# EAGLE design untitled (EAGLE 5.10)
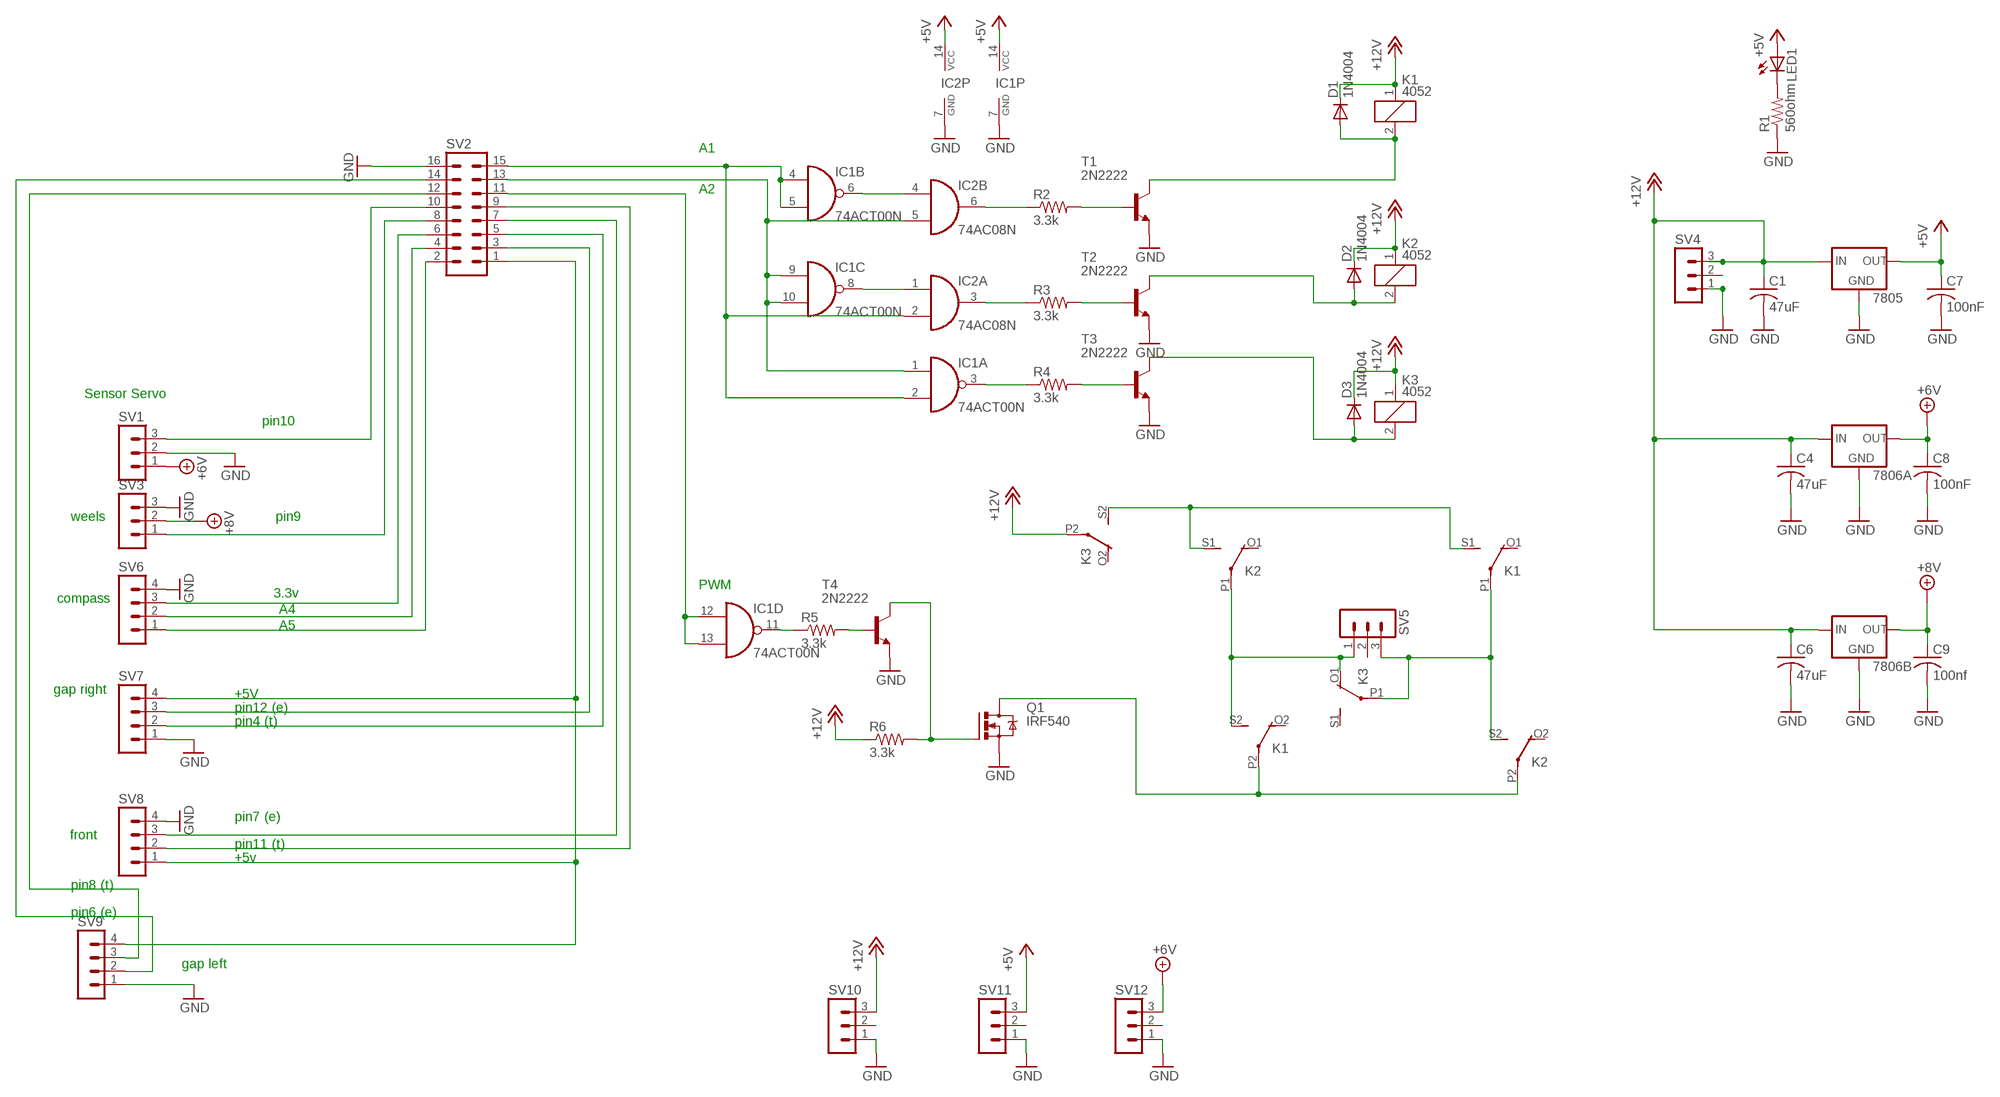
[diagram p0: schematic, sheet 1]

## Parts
7805  78XXL  [78XXL]
7806A  78XXL  [78XXL]
7806B  78XXL  [78XXL]
C1  47uF  C-US025-025X050  [C025-025X050]
C4  47uF  C-US025-025X050  [C025-025X050]
C6  47uF  C-US025-025X050  [C025-025X050]
C7  100nF  C-US025-024X044  [C025-024X044]
C8  100nF  C-US025-024X044  [C025-024X044]
C9  100nf  C-US025-024X044  [C025-024X044]
D1  1N4004  [DO41-10]
D2  1N4004  [DO41-10]
D3  1N4004  [DO41-10]
IC1  74ACT00N  [DIL14]
IC2  74AC08N  [DIL14]
K1  4052  [F4052]
K2  4052  [F4052]
K3  4052  [F4052]
LED1  LED5MM  [LED5MM]
Q1  IRF540  [TO220BV]
R1  560ohm  R-US_0204/7  [0204/7]
R2  3.3k  R-US_0204/7  [0204/7]
R3  3.3k  R-US_0204/7  [0204/7]
R4  3.3k  R-US_0204/7  [0204/7]
R5  3.3k  R-US_0204/7  [0204/7]
R6  3.3k  R-US_0204/7  [0204/7]
SV1  MA03-1  [MA03-1]
SV2  MA08-2  [MA08-2]
SV3  MA03-1  [MA03-1]
SV4  MA03-1  [MA03-1]
SV5  MA03-1  [MA03-1]
SV6  MA04-1  [MA04-1]
SV7  MA04-1  [MA04-1]
SV8  MA04-1  [MA04-1]
SV9  MA04-1  [MA04-1]
SV10  MA03-1  [MA03-1]
SV11  MA03-1  [MA03-1]
SV12  MA03-1  [MA03-1]
T1  2N2222  [TO92-EBC-OVAL]
T2  2N2222  [TO92-EBC-OVAL]
T3  2N2222  [TO92-EBC-OVAL]
T4  2N2222  [TO92-EBC-OVAL]

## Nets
+5V: 7805.OUT C7.1 IC1.14(P:VCC) IC2.14(P:VCC) LED1.A SV11.3
+7V [isxios]: 7806A.OUT C8.1 SV1.1 SV12.3 ; supply symbol labelled +6V
+8V [isxios]: 7806B.OUT C9.1 SV3.2
+12V [isxios]: 7805.IN 7806A.IN 7806B.IN C1.1 C4.1 C6.1 D1.C D2.C D3.C K1.1 K2.1 K3.1 K3.P2(3:P) R6.1 SV4.3 SV10.3
GND: 7805.GND 7806A.GND 7806B.GND C1.2 C4.2 C6.2 C7.2 C8.2 C9.2 IC1.7(P:GND) IC2.7(P:GND) Q1.S R1.1 SV1.2 SV2.16 SV3.3 SV4.1 SV6.4 SV7.1 SV8.4 SV9.1 SV10.1 SV11.1 SV12.1 T1.E T2.E T3.E T4.E
N$1: SV2.2 SV6.1
N$2: LED1.K(C) R1.2
N$3 [isxios]: K1.P2(3:P) K2.P2(3:P) Q1.D
N$4: IC1.2(A:I1) IC1.4(B:I0) IC1.5(B:I1) IC2.2(A:I1) SV2.15
N$5: IC1.6(B:O) IC2.4(B:I0)
N$6: IC1.1(A:I0) IC1.9(C:I0) IC1.10(C:I1) IC2.5(B:I1) SV2.13
N$7: IC1.8(C:O) IC2.1(A:I0)
N$8: IC2.6(B:O) R2.1
N$9: R2.2 T1.B
N$10: IC2.3(A:O) R3.1
N$11: R3.2 T2.B
N$12: IC1.3(A:O) R4.1
N$13: R4.2 T3.B
N$14 [isxios]: D1.A K1.2 T1.C
N$15 [isxios]: D2.A K2.2 T2.C
N$16 [isxios]: D3.A K3.2 T3.C
N$17: SV2.4 SV6.2
N$18: SV2.6 SV6.3
N$19: SV2.8 SV3.1
N$20: SV1.3 SV2.10
N$21: IC1.12(D:I0) IC1.13(D:I1) SV2.11
N$22: IC1.11(D:O) R5.1
N$23: R5.2 T4.B
N$24 [isxios]: Q1.G R6.2 T4.C
N$25 [isxios]: K1.S1(2:S) K2.S1(2:S) K3.S2(3:S)
N$26 [isxios]: K1.P1(2:P) K2.S2(3:S) K3.P1(2:P) SV5.3
N$27 [isxios]: K1.S2(3:S) K2.P1(2:P) K3.O1(2:O) SV5.1
N$28: SV2.1 SV7.4 SV8.1 SV9.4
N$29: SV2.3 SV7.3
N$30: SV2.5 SV7.2
N$31: SV2.7 SV8.3
N$32: SV2.9 SV8.2
N$33: SV2.12 SV9.3
N$34: SV2.14 SV9.2
Unconnected: IC2.8(C:O) IC2.9(C:I0) IC2.10(C:I1) IC2.11(D:O) IC2.12(D:I0) IC2.13(D:I1) K1.O1(2:O) K1.O2(3:O) K2.O1(2:O) K2.O2(3:O) K3.O2(3:O) K3.S1(2:S) SV4.2 SV5.2 SV10.2 SV11.2 SV12.2

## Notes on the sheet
- A1
- A2
- Sensor Servo
- pin10
- weels | pin9
- PWM
- 3.3v
- compass
- A4
- A5
- gap right
- +5V
- pin12 (e)
- pin4 (t)
- pin7 (e)
- front
- pin11 (t)
- +5v
- pin8 (t)
- pin6 (e)
- gap left

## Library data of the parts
7805 7806A 7806B = v-reg:78XXL: VOLTAGE REGULATOR
C1 C4 C6 = adafruit:C-US: CAPACITOR, American symbol
C7-C9 = rcl:C-US: CAPACITOR, American symbol
D1-D3 = adafruit:1N4004: DIODE
IC1 = 74xx-eu:74*00: Quad 2-input NAND gate
IC2 = 74xx-eu:74*08: Quad 2-input AND gate
K1-K3 = relay:4052: RELAY 2 x switch, Finder
LED1 = adafruit:LED: LED
Q1 = transistor-power:IRF540: HEXFET Power MOSFET
R1 = rcl:R-US_: RESISTOR, American symbol
R2-R6 = adafruit:R-US_: RESISTOR, American symbol
SV1 SV3-SV5 SV10-SV12 = con-lstb:MA03-1: PIN HEADER
SV2 = con-lstb:MA08-2: PIN HEADER
SV6-SV9 = con-lstb:MA04-1: PIN HEADER
T1-T4 = adafruit:2N2222: NPN TRANSISTOR Big oval pads

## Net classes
0 default: width 0.8 mm
1 isxios: width 1.6 mm, drill 0.127 mm

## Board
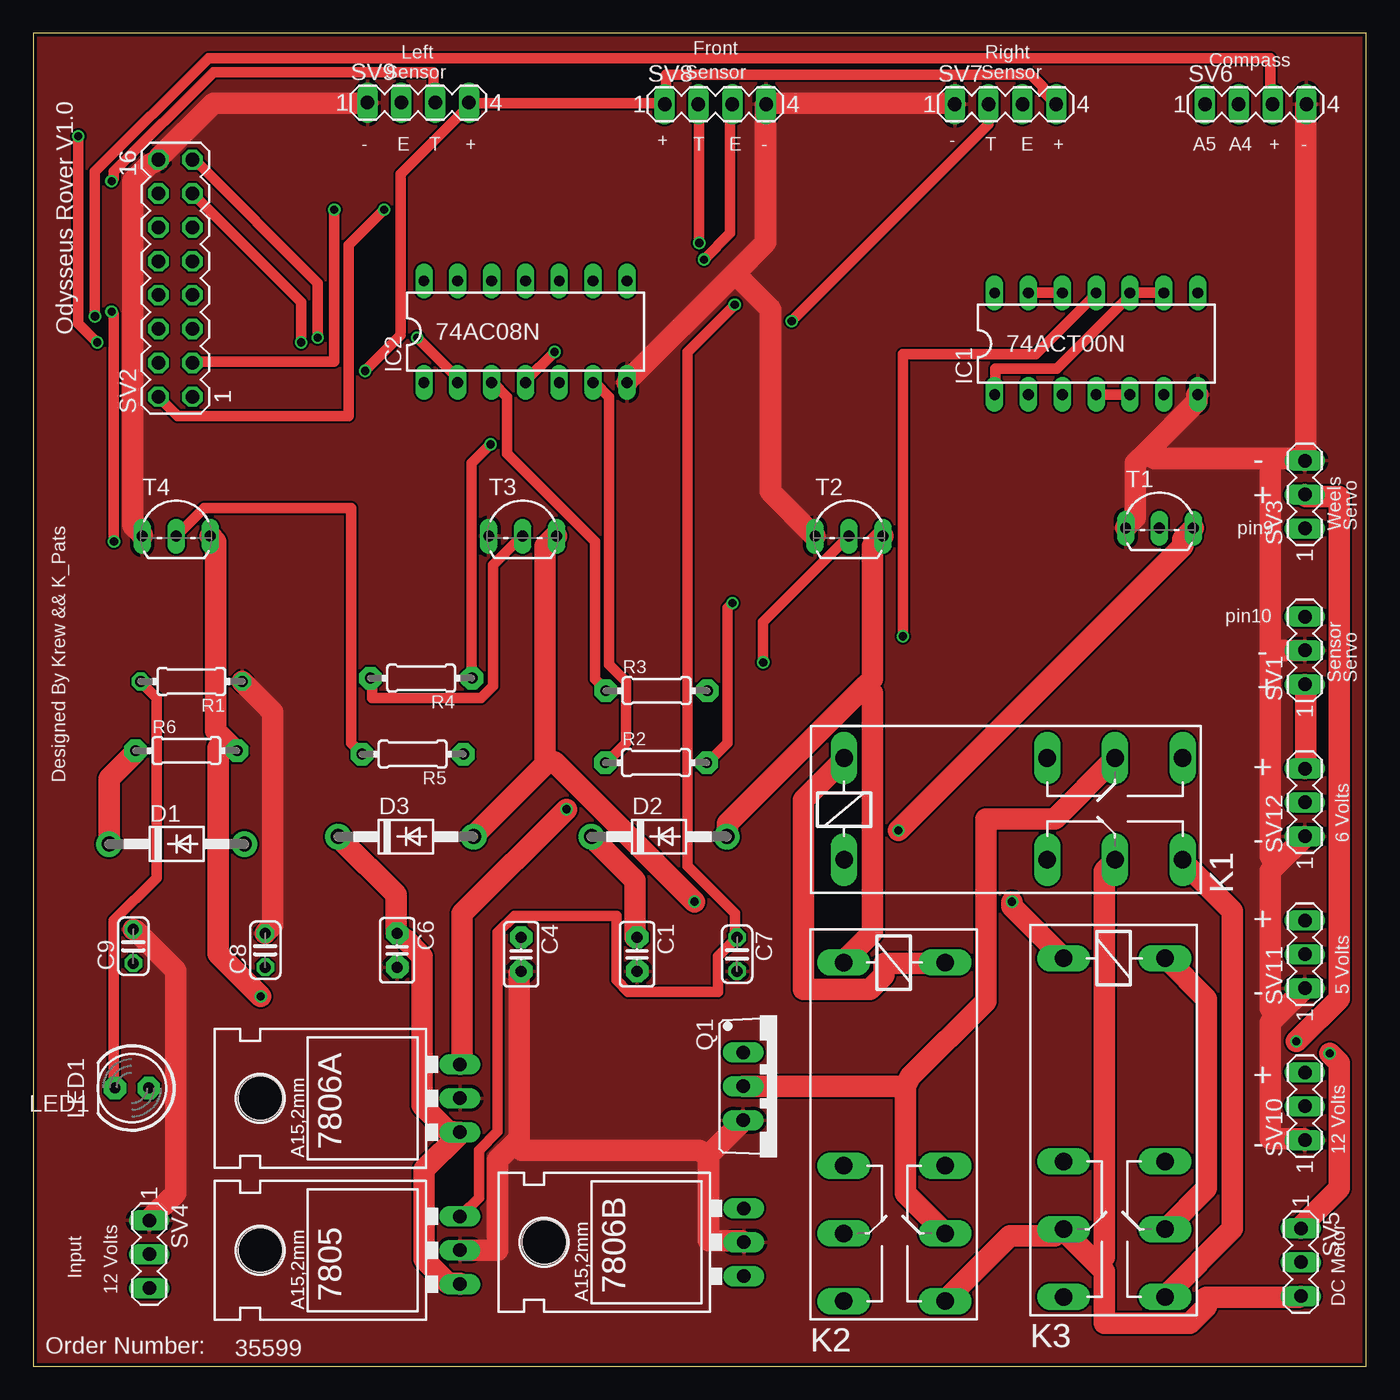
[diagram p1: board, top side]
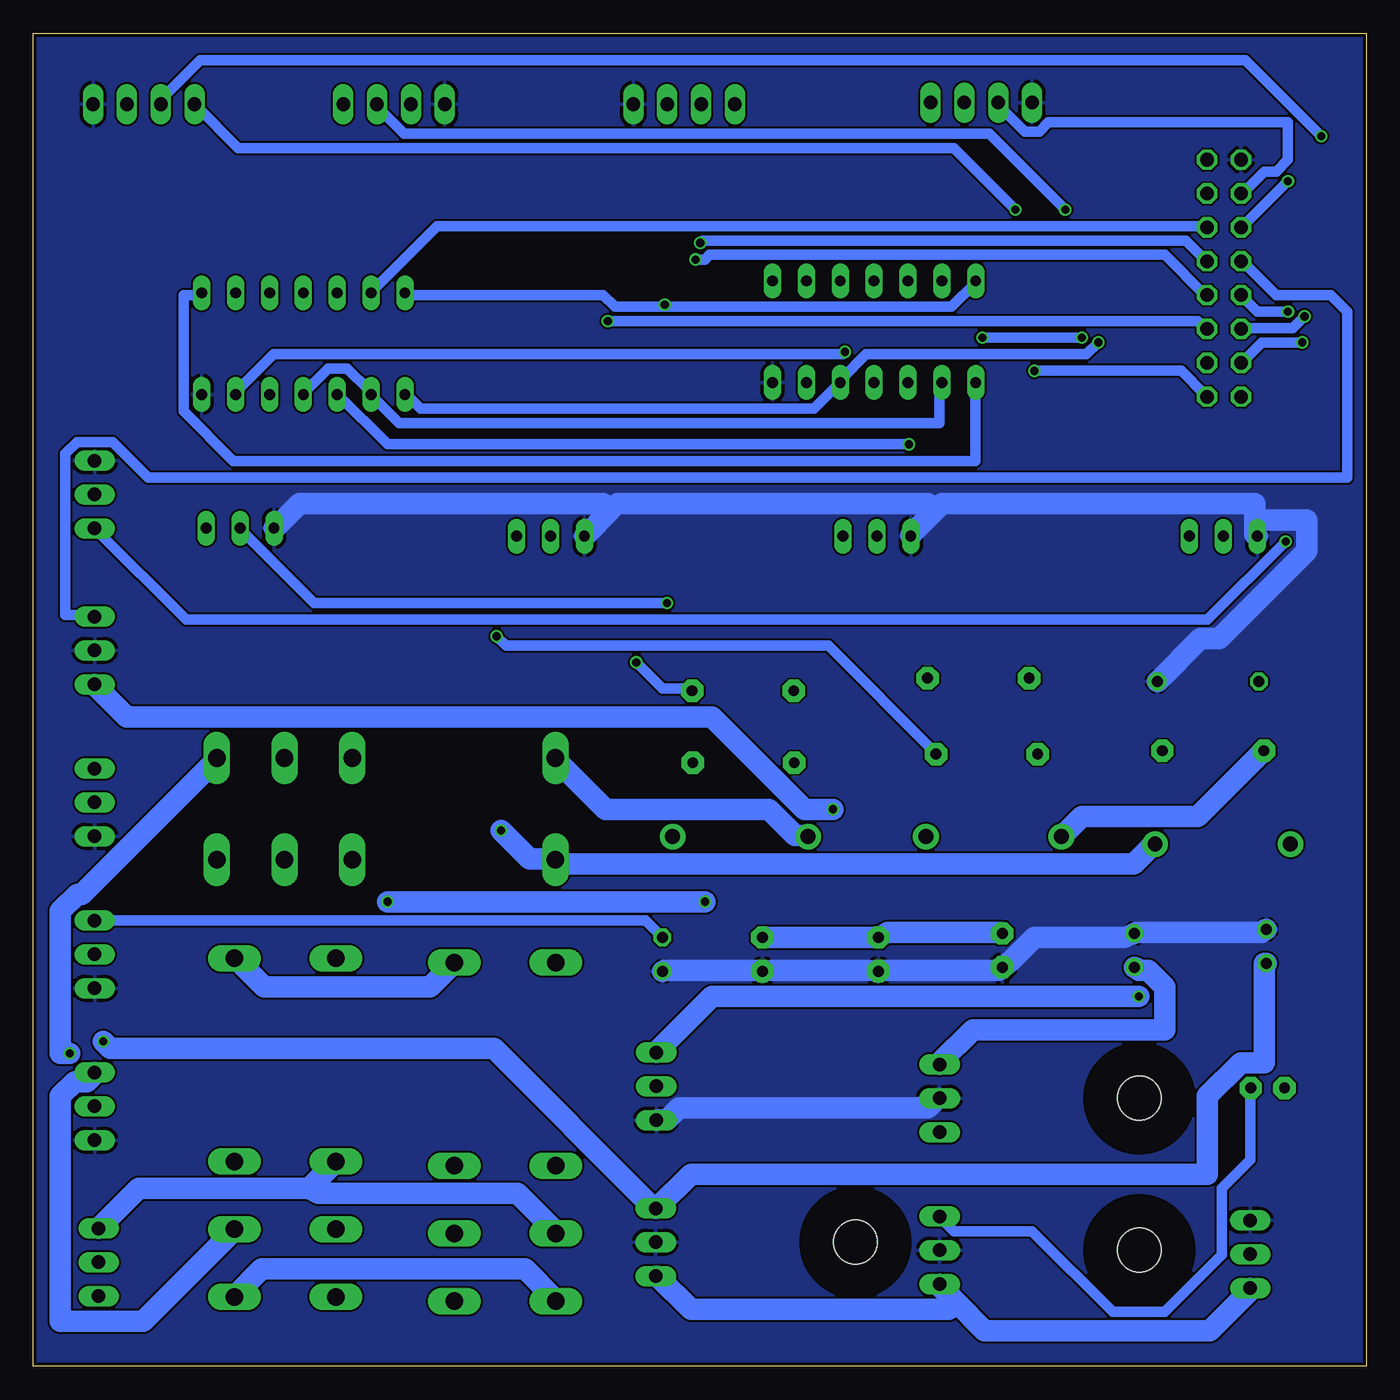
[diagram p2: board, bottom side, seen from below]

Size 100 x 100 mm. Coordinates in mm from the lower left corner, seen from the top.
Outline: 0,0 100,0 100,100 0,100 0,0
Copper layers (1*16): Top 0.035mm / dielectric 1.5mm / Bottom 0.035mm
Design rules "Fusion_eagle_rule_v1.1": minimum track width 6mil, minimum drill 12mil, track to track 6mil, track to pad 6mil, pad to pad 6mil, via to via 6mil, smd to smd 0mil, copper to edge 10mil, drill to drill 10mil, minimum pad ring 10mil, minimum via ring 6mil, stop-mask expansion 2mil, vias tented up to drill 100mil, thermal gap 10mil

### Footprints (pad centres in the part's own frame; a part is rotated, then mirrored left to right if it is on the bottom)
78XXL = drill 1.016 long: GND 0,-3.81; IN -2.54,-3.81; OUT 2.54,-3.81 | hole 3.302: 0,11.176
C025-025X050 = drill 0.813 pad 1.676 octagon: 1 -1.27,0; 2 1.27,0
C025-024X044 = drill 0.813 octagon: 1 -1.27,0; 2 1.27,0
DO41-10 = drill 1.118 pad 1.93 round: A 5.08,0; C -5.08,0
DIL14 = drill 0.813 long: 1 -7.62,-3.81; 2 -5.08,-3.81; 3 -2.54,-3.81; 4 0,-3.81; 5 2.54,-3.81; 6 5.08,-3.81; 7 7.62,-3.81; 8 7.62,3.81; 9 5.08,3.81; 10 2.54,3.81; 11 0,3.81; 12 -2.54,3.81; 13 -5.08,3.81; 14 -7.62,3.81
F4052 = drill 1.321 long: 1 -3.81,3.81; 2 -3.81,-3.81; O1 11.43,-3.81; O2 11.43,3.81; P1 16.51,-3.81; P2 16.51,3.81; S1 21.59,-3.81; S2 21.59,3.81
LED5MM = drill 0.813 pad 1.676 octagon: A -1.27,0; K 1.27,0
TO220BV = drill 1.016 long: D 0,-2.54; G -2.54,-2.54; S 2.54,-2.54
0204/7 = drill 0.813 octagon: 1 -3.81,0; 2 3.81,0
0204/7' = drill 0.813 pad 1.676 octagon: 1 -3.81,0; 2 3.81,0
MA03-1 = drill 1.016 long: 1 -2.54,0; 2 0,0; 3 2.54,0
MA08-2 = drill 1.016 octagon: 1 -8.89,-1.27; 2 -8.89,1.27; 3 -6.35,-1.27; 4 -6.35,1.27; 5 -3.81,-1.27; 6 -3.81,1.27; 7 -1.27,-1.27; 8 -1.27,1.27; 9 1.27,-1.27; 10 1.27,1.27; 11 3.81,-1.27; 12 3.81,1.27; 13 6.35,-1.27; 14 6.35,1.27; 15 8.89,-1.27; 16 8.89,1.27
MA04-1 = drill 1.016 long: 1 -3.81,0; 2 -1.27,0; 3 1.27,0; 4 3.81,0
TO92-EBC-OVAL = drill 0.813 long: B 0,-1.27; C 2.54,-1.27; E -2.54,-1.27

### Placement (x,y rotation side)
7805  28.2,8.7 90 top
7806A  28.2,20.1 90 top
7806B  49.5,9.3 90 top
C1  45.3,30.9 270 top
C4  36.6,30.9 270 top
C6  27.3,31.2 270 top
C7  52.8,30.9 270 top
C8  17.4,31.2 90 top
C9  7.5,31.5 90 top
D1  10.76,39.17 0 top
D2  46.95,39.73 0 top
D3  27.95,39.73 0 top
IC1  79.74,76.71 0 top
IC2  36.92,77.61 0 top
K1  64.64,41.82 0 top
K2  64.61,26.47 270 top
K3  81.11,26.79 270 top
LED1  7.39,20.87 180 top
Q1  55.8,21 270 top
R1  11.86,51.37 180 top
R2  3.3k  [0204/7']  46.72,45.28 0 top
R3  3.3k  [0204/7']  46.76,50.68 0 top
R4  3.3k  [0204/7']  29.1,51.62 180 top
R5  3.3k  [0204/7']  28.46,45.92 180 top
R6  3.3k  [0204/7']  11.48,46.18 0 top
SV1  95.4,53.7 90 top
SV2  10.66,81.63 90 top
SV3  95.4,65.4 90 top
SV4  8.7,8.4 270 top
SV5  95.1,7.8 270 top
SV6  91.71,94.68 0 top
SV7  72.94,94.68 0 top
SV8  51.17,94.68 0 top
SV9  28.88,94.8 0 top
SV10  95.4,19.5 90 top
SV11  95.4,30.9 90 top
SV12  95.4,42.3 90 top
T1  84.49,64.14 0 top
T2  61.2,63.54 0 top
T3  36.71,63.54 0 top
T4  10.72,63.54 0 top

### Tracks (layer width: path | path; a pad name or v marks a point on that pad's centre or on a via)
+5V  (via drill 0.61)
  Top 0.8: 7805.OUT 32.18,11.38 33.43,12.62 33.43,16.18 34.85,17.6 34.85,32.54 36.09,33.78 43.74,33.78 43.74,28.98 44.63,28.09 51.38,28.09 51.38,30.76 52.63,32 C7.1 52.63,32.54 52.63,33.96 49.07,37.52 49.07,76.1 v52.63,79.65
  Bottom 0.8: 52.63,79.48 56.36,79.48 57.25,80.37 72.01,80.37 IC1.14 | 52.63,79.48 31.11,79.48 29.34,81.25 IC2.14 | 7805.OUT 32,11.2 30.94,10.13 25.07,10.13 19.02,4.09 15.11,4.09 10.85,8.36 10.85,13.34 8.71,15.47 8.71,20.8 LED1.A | C7.1 52.81,32.18 54.05,33.43 95.3,33.43 SV11.3 | v52.63,79.65 52.63,79.48
+7V  (via drill 0.61)
  Top 1.6: SV12.3 95.48,44.98 95.48,51.03 SV1.1 | v40.01,41.78 32.18,33.96 32.18,22.76 7806A.OUT
  Bottom 1.6: C8.1 17.25,29.87 17.07,29.69 16.36,29.69 15.11,28.45 15.11,25.25 29.52,25.25 32,22.76 7806A.OUT | v40.01,41.78 42.14,41.78 49.07,48.72 92.99,48.72 95.3,51.03 SV1.1
+8V  (via drill 0.61)
  Top 1.6: v94.77,24.36 97.97,27.56 97.97,65.25 95.48,65.25 SV3.2
  Bottom 1.6: C9.1 7.64,30.23 7.64,22.76 9.42,22.76 11.91,20.27 11.91,14.4 50.67,14.4 53.16,11.91 7806B.OUT 53.87,12.27 65.43,23.82 94.23,23.82 v94.77,24.36
+12V
  Top 1.6: 7805.IN 32,6.22 31.11,6.22 29.34,8 29.34,14.76 32,17.42 7806A.IN 31.11,17.6 29.16,19.56 29.16,30.76 27.91,32 C6.1 27.2,32.54 27.2,35.38 22.94,39.65 D3.C | K3.1 84.99,30.58 88.01,27.56 88.01,13.34 84.99,10.31 K3.P2 | R6.1 7.64,46.05 5.69,44.09 5.69,39.29 D1.C | D2.C 41.96,39.65 45.16,36.45 45.16,32.18 C1.1 | K2.1 68.28,30.23 63.83,30.23 63.83,29.34 62.76,28.27 57.78,28.27 57.78,42.49 60.81,45.52 K1.1
  Bottom 1.6: 30.76,4.8 32,6.04 7805.IN | 30.76,4.8 28.63,2.67 11.73,2.67 8.71,5.69 SV4.3 | 7806B.IN 53.16,6.76 50.67,4.27 31.29,4.27 30.76,4.8 | K2.1 68.45,30.23 70.23,28.45 82.68,28.45 84.81,30.58 K3.1 | SV10.3 95.48,21.87 96.01,21.34 96.9,21.34 97.97,20.27 97.97,3.38 91.75,3.38 84.99,10.13 K3.P2 | C1.1 45.16,32.18 36.63,32.18 C4.1 35.92,32.54 27.38,32.54 C6.1 | K1.1 60.81,45.52 57.07,41.78 44.81,41.78 42.85,39.83 41.96,39.83 D2.C | R6.1 7.82,46.05 12.62,41.25 21.34,41.25 22.76,39.83 D3.C
GND
  Top 1.6: 93.34,26.31 95.3,28.27 SV11.1 | 93.34,26.31 92.81,25.78 92.81,17.07 95.3,17.07 SV10.1 | 93.34,37.69 92.81,37.16 92.81,26.85 93.34,26.31 | 93.34,37.69 95.3,39.65 SV12.1 | 92.81,53.7 95.3,53.7 SV1.2 | 92.81,53.7 92.81,38.23 93.34,37.69 | 83.57,68.63 87.3,72.36 87.3,72.9 IC1.7 | 83.57,68.63 82.68,67.74 82.68,63.65 81.97,62.94 T1.E | 92.81,68.1 84.1,68.1 83.57,68.63 | 92.81,68.1 95.3,68.1 | 95.3,68.1 SV3.3 | SV6.4 95.48,94.59 95.48,68.81 95.3,68.1 | 92.81,68.1 92.81,53.7 | 50.67,15.82 50.67,9.42 53.16,9.42 7806B.GND | 50.67,15.82 53.16,18.31 Q1.S | 36.09,16.71 36.45,17.07 36.45,29.52 C4.2 | 36.09,16.71 34.85,15.47 34.85,8.71 32.18,8.71 7805.GND | 50.67,15.82 49.96,16.18 36.63,16.18 36.09,16.71 | R1.1 15.82,51.21 17.96,49.07 17.96,33.07 17.42,32.54 C8.2 | SV4.1 8.71,11.02 10.67,12.98 10.67,29.69 7.64,32.72 C9.2 | 52.63,81.97 54.94,84.28 54.94,94.59 SV8.4 55.65,94.77 68.99,94.77 SV7.1 | 52.63,81.97 44.63,73.97 IC2.7 | SV9.1 25.07,94.77 13.51,94.77 9.42,90.68 SV2.16 8.71,90.14 7.47,88.9 7.47,63.12 8.18,62.41 T4.E | 52.63,81.97 55.3,79.3 55.3,65.61 58.5,62.41 T2.E
  Bottom 1.6: 7806A.GND 32.18,20.09 32.89,19.38 51.56,19.38 52.45,18.49 53.16,18.49 Q1.S | C7.2 52.63,29.69 45.34,29.69 C1.2 44.63,29.69 37.34,29.69 C4.2 36.45,29.69 27.56,29.69 27.38,29.87 C6.2 26.67,30.4 24.89,32.18 18.14,32.18 C8.2 17.25,32.54 7.82,32.54 7.64,32.72 C9.2 | 8.36,63.48 8.36,64.72 31.83,64.72 32.36,64.19 | 8.36,63.48 8.36,62.41 T4.E | 32.36,64.19 34.14,62.41 T3.E | 56.72,64.19 56.19,64.72 32.89,64.72 32.36,64.19 | 56.72,64.19 58.5,62.41 T2.E | R1.1 15.65,51.38 12.45,54.59 11.02,54.59 4.45,61.16 4.45,63.48 8.36,63.48 | T1.E 81.79,62.94 80.01,64.72 57.25,64.72 56.72,64.19
  pour Top: 0,100 100,100 100,0 0,0
  pour Bottom: 0,100 100,100 100,0 0,0
N$1  (via drill 0.61)
  Top 0.8: v26.31,86.77 23.65,84.1 23.65,71.3 10.85,71.3 9.42,72.72 SV2.2
  Bottom 0.8: v26.31,86.77 30.94,91.39 84.63,91.39 87.83,94.59 SV6.1
N$2
  Top 0.8: R1.2 8.18,51.21 9.25,50.14 9.25,36.63 6.04,33.43 6.04,20.98 LED1.K
N$3
  Top 1.6: 65.43,20.98 53.34,20.98 Q1.D | 65.43,20.98 65.43,12.98 68.28,10.13 K2.P2 | K1.P2 81.08,45.52 76.63,41.07 71.48,41.07 71.48,27.38 65.79,21.69 65.43,20.98
N$4  (via drill 0.61)
  Top 0.8: IC1.4 79.83,72.9 82.14,72.9 IC1.5 | v21.34,77.17 21.34,81.25 12.09,90.5 SV2.15 | v28.8,77.17 31.83,74.14 31.83,73.97 IC2.2
  Bottom 0.8: IC2.2 32,73.79 32,70.76 72.54,70.76 74.68,72.9 IC1.2 74.85,73.25 76.45,74.85 77.88,74.85 79.65,73.08 IC1.4 | v21.34,77.17 v28.8,77.17
N$5  (via drill 0.61)
  Top 0.8: v39.12,76.1 36.98,73.97 IC2.4
  Bottom 0.8: v39.12,76.1 39.29,75.92 81.97,75.92 84.81,73.08 IC1.6
N$6  (via drill 0.61)
  Top 0.8: IC1.9 84.81,80.54 82.32,80.54 IC1.10 82.14,80.19 76.81,74.85 72.19,74.85 72.19,73.08 IC1.1 | v20.09,76.81 20.09,79.83 12.09,87.83 SV2.13
  Bottom 0.8: IC1.1 72.01,72.9 70.94,71.83 41.43,71.83 39.47,73.79 IC2.5 39.29,74.14 37.52,75.92 20.98,75.92 v20.09,76.81
N$7
  Bottom 0.8: IC2.1 29.34,73.79 29.34,67.92 84.99,67.92 88.72,71.65 88.72,80.37 87.48,80.37 IC1.8
N$8
  Top 0.8: IC2.6 42.14,73.79 43.2,72.72 43.2,52.63 44.45,51.38 44.45,46.76 43.03,45.34 R2.1
N$9  (via drill 0.61)
  Top 0.8: v52.45,57.25 52.09,56.9 52.09,46.76 50.67,45.34 R2.2
  Bottom 0.8: v52.45,57.25 78.94,57.25 84.45,62.76 T1.B
N$10
  Top 0.8: IC2.3 34.49,73.79 35.56,72.72 35.56,68.45 42.14,61.87 42.14,51.56 42.85,50.85 R3.1
N$11  (via drill 0.61)
  Top 0.8: v54.76,52.81 54.76,55.83 61.16,62.23 T2.B
  Bottom 0.8: v54.76,52.81 52.81,50.85 50.67,50.85 R3.2
N$12  (via drill 0.61)
  Top 0.8: v34.31,69.16 32.89,67.74 32.89,51.74 R4.1
  Bottom 0.8: v34.31,69.16 73.43,69.16 77.17,72.9 IC1.3
N$13
  Top 0.8: T3.B 36.63,62.23 34.49,60.1 34.49,51.03 33.6,50.14 25.43,50.14 25.43,51.56 R4.2
N$14  (via drill 0.61)
  Top 1.6: v64.9,40.18 86.23,61.52 86.23,62.05 86.94,62.76 T1.C
  Bottom 1.6: v64.9,40.18 62.76,38.05 60.98,38.05 K1.2 60.1,37.69 17.42,37.69 16,39.12 D1.A
N$15
  Top 1.6: 62.41,51.03 52.09,40.72 52.09,39.83 D2.A | 62.41,51.03 62.94,51.56 62.94,61.52 63.65,62.23 T2.C | K2.2 60.81,30.4 62.94,32.54 62.94,50.49 62.41,51.03
N$16  (via drill 0.61)
  Top 1.6: 38.41,45.34 38.41,45.16 33.07,39.83 D3.A | 38.41,45.34 38.41,61.52 39.12,62.23 T3.C | v73.43,34.85 73.43,34.49 77.17,30.76 K3.2 | v49.61,34.85 39.12,45.34 38.41,45.34
  Bottom 1.6: v49.61,34.85 v73.43,34.85
N$17  (via drill 0.61)
  Top 0.8: v4.8,76.81 3.38,78.23 v3.38,92.28
  Bottom 0.8: v4.8,76.81 7.82,76.81 9.25,75.39 SV2.4 | v3.38,92.28 9.07,97.97 87.48,97.97 90.32,95.12 90.32,94.77 SV6.2
N$18  (via drill 0.61)
  Top 0.8: v4.62,78.77 4.62,89.61 13.16,98.15 92.81,98.15 92.81,94.77 SV6.3
  Bottom 0.8: v4.62,78.77 5.51,77.88 9.25,77.88 SV2.6
N$19  (via drill 0.61)
  Top 0.8: v5.87,79.12 6.04,78.94 v6.04,61.87
  Bottom 0.8: v5.87,79.12 8.18,79.12 9.25,80.19 SV2.8 | v6.04,61.87 11.91,56.01 88.54,56.01 95.3,62.76 SV3.1
N$20
  Bottom 0.8: SV2.10 9.25,82.86 6.76,80.37 2.67,80.37 1.42,79.12 1.42,66.67 91.39,66.67 94.06,69.34 96.72,69.34 97.61,68.45 97.61,56.36 95.48,56.36 SV1.3
N$21
  Top 0.8: IC1.13 74.68,80.54 77.17,80.54 IC1.12
  Bottom 0.8: SV2.11 12.09,85.52 69.7,85.52 74.68,80.54 IC1.13
N$22  (via drill 0.61)
  Top 0.8: v65.25,54.76 65.25,75.92 75.21,75.92 79.65,80.37 IC1.11
  Bottom 0.8: v65.25,54.76 64.54,54.05 40.36,54.05 32.36,46.05 R5.1
N$23
  Top 0.8: T4.B 10.85,62.41 12.8,64.36 23.82,64.36 23.82,46.76 24.54,46.05 R5.2
N$24  (via drill 0.61)
  Top 1.6: 14.4,46.94 15.11,46.23 R6.2 | 14.4,46.94 13.69,47.65 13.69,61.87 13.34,62.23 T4.C | v17.07,27.74 13.87,30.94 13.87,46.41 14.4,46.94
  Bottom 1.6: v17.07,27.74 49.07,27.74 53.16,23.65 Q1.G
N$25
  Top 1.6: K1.S1 86.23,37.87 89.97,34.14 89.97,10.31 84.99,5.33 K3.S2
  Bottom 1.6: K2.S1 60.81,4.98 63.12,7.29 82.86,7.29 84.81,5.33 K3.S2
N$26
  Top 1.6: 79.83,7.64 77.34,10.13 K3.P1 76.63,9.78 73.25,9.78 68.45,4.98 K2.S2 | 79.83,7.64 80.37,7.11 80.37,3.2 86.77,3.2 88.01,4.45 88.01,5.16 94.94,5.16 SV5.3 | K1.P1 81.08,37.87 80.37,37.16 80.37,8.18 79.83,7.64
N$27  (via drill 0.61)
  Top 1.6: v97.26,23.47 97.97,22.76 97.97,13.34 95.12,10.49 SV5.1
  Bottom 1.6: 79.3,13.34 92.1,13.34 94.94,10.49 SV5.1 | 79.3,13.34 77.34,15.29 K3.O1 | K2.P1 60.81,10.13 63.65,12.98 78.59,12.98 79.3,13.34 | v97.26,23.47 97.97,23.47 97.97,34.14 96.72,35.38 96.37,35.38 86.23,45.52 K1.S2
N$28  (via drill 0.61)
  Top 0.8: v24.89,74.68 27.56,77.34 27.56,89.43 32.54,94.41 32.54,94.77 SV9.4 33.07,94.77 47.3,94.77 SV8.1 47.47,95.12 47.47,96.9 74.85,96.9 75.74,96.01 75.74,95.66 76.63,94.77 SV7.4
  Bottom 0.8: v24.89,74.68 13.87,74.68 12.09,72.9 SV2.1
N$29  (via drill 0.61)
  Top 0.8: v22.58,86.77 22.58,75.39 12.09,75.39 SV2.3
  Bottom 0.8: v22.58,86.77 28.27,92.46 72.19,92.46 74.32,94.59 SV7.3
N$30  (via drill 0.61)
  Top 0.8: v56.9,78.41 71.65,93.17 71.65,94.59 SV7.2
  Bottom 0.8: v56.9,78.41 12.62,78.41 12.09,77.88 SV2.5
N$31  (via drill 0.61)
  Top 0.8: v50.32,83.03 52.27,84.99 52.27,94.59 SV8.3
  Bottom 0.8: v50.32,83.03 49.61,83.03 49.25,83.39 15.11,83.39 12.09,80.37 SV2.7
N$32  (via drill 0.61)
  Top 0.8: v49.96,84.28 49.96,94.59 SV8.2
  Bottom 0.8: v49.96,84.28 49.78,84.45 13.51,84.45 12.09,83.03 SV2.9
N$33  (via drill 0.61)
  Top 0.8: v5.87,88.9 6.04,89.08 6.04,89.61 13.51,97.08 30.05,97.08 30.05,94.94 SV9.3
  Bottom 0.8: v5.87,88.9 9.25,85.52 SV2.12
N$34
  Bottom 0.8: SV2.14 9.25,88.01 7.64,89.61 6.76,89.61 5.87,90.5 5.87,93.34 23.82,93.34 24.54,92.63 25.6,92.63 27.74,94.77 SV9.2

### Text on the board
_tsilk: Left | Front | Right | Compass | Sensor | Sensor | Sensor | + | - | - | E | T | + | T | E | - | T | E | + | A5 | A4 | + | - | 16 | Odysseus Rover V1.0 | 74AC08N | 74ACT00N | 1 | - | + | Weels | Servo | pin9 | pin10 | - | Sensor | Servo | + | Designed By Krew && K_Pats | + | - | 6 Volts | K1 | + | 5 Volts | - | + | LED1 | A15,2mm | 7806A | - | 12 Volts | Input | 12 Volts | 7805 | A15,2mm | 7806B | A15,2mm | DC Motor | Order Number: | 35599 | K2 | K3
